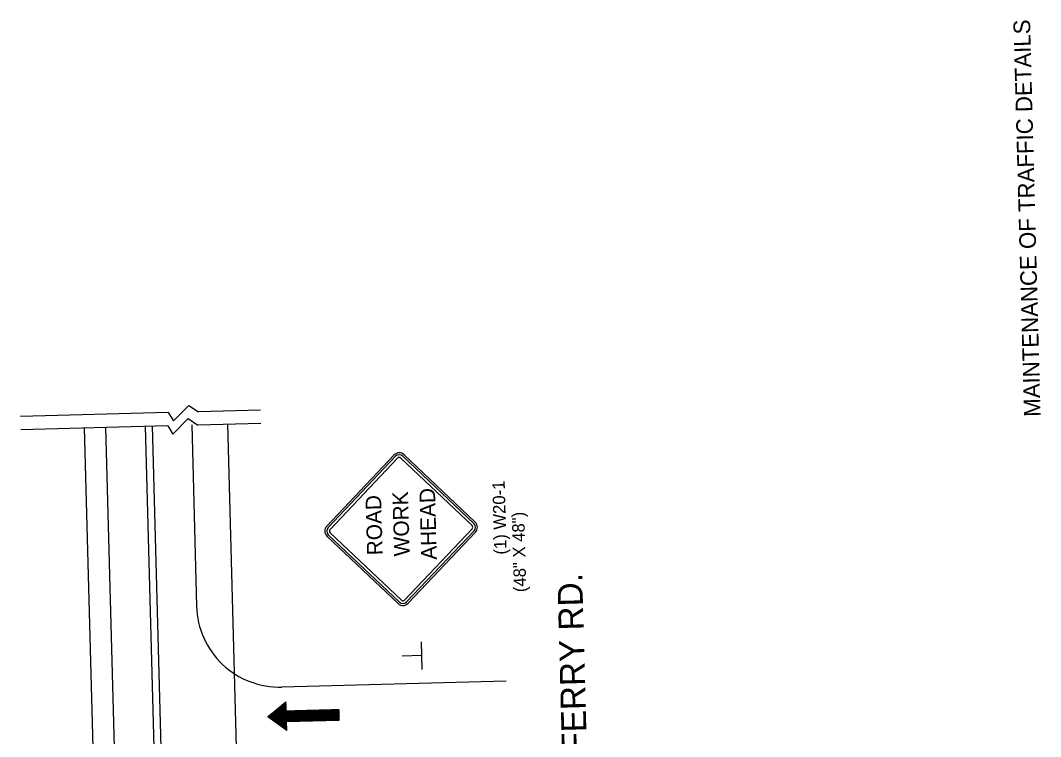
# Model space of a CAD drawing. Extents: x 1929653 to 1931621, y 596452 to 600944.
# Drawn here: x 1930855 to 1931592, y 598042 to 598560 of the extents above; entities that cross this region are included whole.
import ezdxf

# ---------------------------------------------------------------- set-up
doc = ezdxf.new("R2010")
doc.units = 0
for name, color, linetype in [('P_TC_Signs_Temporary', 7, 'Continuous'), ('R_Border', 7, 'Continuous'), ('R_Draft', 7, 'Continuous')]:
    doc.layers.add(name, color=color, linetype=linetype)

msp = doc.modelspace()

# ---------------------------------------------------------------- linework, layer by layer
at = {"layer": 'P_TC_Signs_Temporary'}
for p, q in [((1931124.99, 598245.86), (1931076.24, 598194.42)), ((1931126.01, 598244.9), (1931077.26, 598193.45)), ((1931182.62, 598196.28), (1931131.18, 598245.04)), ((1931183.59, 598197.3), (1931132.15, 598246.06)), ((1931127.44, 598243.54), (1931078.69, 598192.1)), ((1931181.27, 598194.85), (1931129.82, 598243.61)), ((1931076.43, 598187.26), (1931127.87, 598138.51)), ((1931077.4, 598188.28), (1931128.84, 598139.53)), ((1931078.75, 598189.71), (1931130.19, 598140.96)), ((1931132.58, 598141.02), (1931181.33, 598192.47)), ((1931134.01, 598139.67), (1931182.76, 598191.11)), ((1931135.03, 598138.7), (1931183.78, 598190.15))]:
    msp.add_line(p, q, dxfattribs=at)
for centre, radius, start, end in [((1931128.66, 598242.38), 5.06, 46.53769, 136.53769), ((1931128.66, 598242.38), 3.66, 46.53769, 136.53769), ((1931128.66, 598242.38), 1.69, 46.53769, 136.53769), ((1931079.91, 598190.94), 5.06, 136.53769, 226.53769), ((1931079.91, 598190.94), 3.66, 136.53769, 226.53769), ((1931180.11, 598193.63), 1.69, 316.53769, 46.53769), ((1931180.11, 598193.63), 3.66, 316.53769, 46.53769), ((1931180.11, 598193.63), 5.06, 316.53769, 46.53769), ((1931079.91, 598190.94), 1.69, 136.53769, 226.53769), ((1931131.35, 598142.18), 5.06, 226.53769, 316.53769), ((1931131.35, 598142.18), 3.66, 226.53769, 316.53769), ((1931131.35, 598142.18), 1.69, 226.53769, 316.53769)]:
    msp.add_arc(centre, radius, start, end, dxfattribs=at)
at = {"layer": 'R_Border'}
for p, q in [((1931038.76, 598060.91), (1931034.33, 598056.24)), ((1931039.54, 598061.55), (1931034.43, 598056.16)), ((1931040.32, 598062.19), (1931034.54, 598056.08)), ((1931041.11, 598062.83), (1931034.64, 598056)), ((1931041.89, 598063.46), (1931034.75, 598055.93)), ((1931042.68, 598064.1), (1931034.85, 598055.85)), ((1931043.46, 598064.74), (1931034.96, 598055.77)), ((1931044.24, 598065.38), (1931035.07, 598055.7)), ((1931045.03, 598066.01), (1931035.17, 598055.62)), ((1931045.81, 598066.65), (1931035.28, 598055.54)), ((1931046.59, 598067.29), (1931035.38, 598055.46)), ((1931046.82, 598067.34), (1931035.49, 598055.39)), ((1931046.82, 598067.16), (1931035.6, 598055.31)), ((1931046.83, 598066.97), (1931035.7, 598055.23)), ((1931046.83, 598066.79), (1931035.81, 598055.16)), ((1931046.84, 598066.61), (1931035.91, 598055.08)), ((1931046.84, 598066.42), (1931036.02, 598055)), ((1931046.85, 598066.24), (1931036.13, 598054.92)), ((1931046.85, 598066.05), (1931036.23, 598054.85)), ((1931046.86, 598065.87), (1931036.34, 598054.77)), ((1931046.86, 598065.69), (1931036.44, 598054.69)), ((1931046.87, 598065.5), (1931036.55, 598054.62)), ((1931046.87, 598065.32), (1931036.66, 598054.54)), ((1931046.88, 598065.14), (1931036.76, 598054.46)), ((1931046.88, 598064.95), (1931036.87, 598054.38)), ((1931046.89, 598064.77), (1931036.97, 598054.31)), ((1931046.89, 598064.58), (1931037.08, 598054.23)), ((1931046.9, 598064.4), (1931037.19, 598054.15)), ((1931046.9, 598064.22), (1931037.29, 598054.07)), ((1931046.91, 598064.03), (1931037.4, 598054)), ((1931046.91, 598063.85), (1931037.5, 598053.92)), ((1931046.92, 598063.67), (1931037.61, 598053.84)), ((1931046.92, 598063.48), (1931037.72, 598053.77)), ((1931046.93, 598063.3), (1931037.82, 598053.69)), ((1931046.93, 598063.11), (1931037.93, 598053.61)), ((1931046.94, 598062.93), (1931038.03, 598053.53)), ((1931046.94, 598062.75), (1931038.14, 598053.46)), ((1931046.95, 598062.56), (1931038.25, 598053.38)), ((1931046.95, 598062.38), (1931038.35, 598053.3)), ((1931046.96, 598062.19), (1931038.46, 598053.23)), ((1931046.96, 598062.01), (1931038.56, 598053.15)), ((1931046.97, 598061.83), (1931038.67, 598053.07)), ((1931046.97, 598061.64), (1931038.78, 598052.99)), ((1931046.98, 598061.46), (1931038.88, 598052.92)), ((1931046.98, 598061.28), (1931038.99, 598052.84)), ((1931046.99, 598061.09), (1931039.09, 598052.76)), ((1931047.07, 598060.99), (1931039.2, 598052.69)), ((1931047.26, 598061), (1931039.31, 598052.61)), ((1931047.44, 598061), (1931039.41, 598052.53)), ((1931047.62, 598061.01), (1931039.52, 598052.45)), ((1931047.81, 598061.01), (1931039.62, 598052.38)), ((1931047.99, 598061.02), (1931039.73, 598052.3)), ((1931048.18, 598061.02), (1931039.84, 598052.22)), ((1931048.36, 598061.03), (1931039.94, 598052.15)), ((1931048.54, 598061.03), (1931040.05, 598052.07)), ((1931048.73, 598061.04), (1931040.15, 598051.99)), ((1931048.91, 598061.04), (1931040.26, 598051.91)), ((1931049.09, 598061.05), (1931040.37, 598051.84)), ((1931049.28, 598061.05), (1931040.47, 598051.76)), ((1931049.46, 598061.06), (1931040.58, 598051.68)), ((1931049.65, 598061.06), (1931040.68, 598051.61)), ((1931049.83, 598061.07), (1931040.79, 598051.53)), ((1931050.01, 598061.07), (1931040.89, 598051.45)), ((1931050.2, 598061.08), (1931041, 598051.37)), ((1931050.38, 598061.08), (1931041.11, 598051.3)), ((1931050.56, 598061.09), (1931041.21, 598051.22)), ((1931050.75, 598061.09), (1931041.32, 598051.14)), ((1931050.93, 598061.1), (1931041.42, 598051.06)), ((1931051.12, 598061.1), (1931041.53, 598050.99)), ((1931051.3, 598061.11), (1931041.64, 598050.91)), ((1931051.48, 598061.11), (1931041.74, 598050.83)), ((1931051.67, 598061.12), (1931041.85, 598050.76)), ((1931051.85, 598061.12), (1931041.95, 598050.68)), ((1931052.03, 598061.13), (1931042.06, 598050.6)), ((1931052.22, 598061.13), (1931042.17, 598050.52)), ((1931052.4, 598061.14), (1931042.27, 598050.45)), ((1931052.59, 598061.14), (1931042.38, 598050.37)), ((1931052.77, 598061.15), (1931042.48, 598050.29)), ((1931052.95, 598061.15), (1931042.59, 598050.22)), ((1931053.14, 598061.16), (1931042.7, 598050.14)), ((1931053.32, 598061.16), (1931042.8, 598050.06)), ((1931053.5, 598061.17), (1931042.91, 598049.98)), ((1931053.69, 598061.17), (1931043.01, 598049.91)), ((1931053.87, 598061.18), (1931043.12, 598049.83)), ((1931054.06, 598061.18), (1931043.23, 598049.75)), ((1931054.24, 598061.19), (1931043.33, 598049.68)), ((1931054.42, 598061.19), (1931043.44, 598049.6)), ((1931054.61, 598061.2), (1931043.54, 598049.52)), ((1931054.79, 598061.2), (1931047.22, 598053.21)), ((1931054.98, 598061.21), (1931047.41, 598053.22)), ((1931055.16, 598061.21), (1931047.59, 598053.22)), ((1931055.34, 598061.22), (1931047.77, 598053.23)), ((1931055.53, 598061.22), (1931047.96, 598053.23)), ((1931055.71, 598061.23), (1931048.14, 598053.24)), ((1931055.89, 598061.23), (1931048.33, 598053.24)), ((1931056.08, 598061.23), (1931048.51, 598053.25)), ((1931056.26, 598061.24), (1931048.69, 598053.25)), ((1931056.45, 598061.24), (1931048.88, 598053.26)), ((1931056.63, 598061.25), (1931049.06, 598053.26)), ((1931056.81, 598061.25), (1931049.24, 598053.27)), ((1931057, 598061.26), (1931049.43, 598053.27)), ((1931057.18, 598061.26), (1931049.61, 598053.28)), ((1931057.36, 598061.27), (1931049.8, 598053.28)), ((1931057.55, 598061.27), (1931049.98, 598053.29)), ((1931057.73, 598061.28), (1931050.16, 598053.29)), ((1931057.92, 598061.28), (1931050.35, 598053.3)), ((1931058.1, 598061.29), (1931050.53, 598053.3)), ((1931058.28, 598061.29), (1931050.71, 598053.31)), ((1931058.47, 598061.3), (1931050.9, 598053.31)), ((1931058.65, 598061.3), (1931051.08, 598053.32)), ((1931058.83, 598061.31), (1931051.27, 598053.32)), ((1931059.02, 598061.31), (1931051.45, 598053.33)), ((1931059.2, 598061.32), (1931051.63, 598053.33)), ((1931059.39, 598061.32), (1931051.82, 598053.34)), ((1931059.57, 598061.33), (1931052, 598053.34)), ((1931059.75, 598061.33), (1931052.19, 598053.35)), ((1931059.94, 598061.34), (1931052.37, 598053.35)), ((1931060.12, 598061.34), (1931052.55, 598053.36)), ((1931060.3, 598061.35), (1931052.74, 598053.36)), ((1931060.49, 598061.35), (1931052.92, 598053.37)), ((1931060.67, 598061.36), (1931053.1, 598053.37)), ((1931060.86, 598061.36), (1931053.29, 598053.38)), ((1931061.04, 598061.37), (1931053.47, 598053.38)), ((1931061.22, 598061.37), (1931053.66, 598053.39)), ((1931061.41, 598061.38), (1931053.84, 598053.39)), ((1931061.59, 598061.38), (1931054.02, 598053.4)), ((1931061.78, 598061.39), (1931054.21, 598053.4)), ((1931061.96, 598061.39), (1931054.39, 598053.41)), ((1931062.14, 598061.4), (1931054.57, 598053.41)), ((1931062.33, 598061.4), (1931054.76, 598053.42)), ((1931062.51, 598061.41), (1931054.94, 598053.42)), ((1931062.69, 598061.41), (1931055.13, 598053.43)), ((1931062.88, 598061.42), (1931055.31, 598053.43)), ((1931063.06, 598061.42), (1931055.49, 598053.44)), ((1931063.25, 598061.43), (1931055.68, 598053.44)), ((1931063.43, 598061.43), (1931055.86, 598053.45)), ((1931063.61, 598061.44), (1931056.04, 598053.45)), ((1931063.8, 598061.44), (1931056.23, 598053.46)), ((1931063.98, 598061.45), (1931056.41, 598053.46)), ((1931064.16, 598061.45), (1931056.6, 598053.47)), ((1931064.35, 598061.46), (1931056.78, 598053.47)), ((1931064.53, 598061.46), (1931056.96, 598053.48)), ((1931064.72, 598061.47), (1931057.15, 598053.48)), ((1931064.9, 598061.47), (1931057.33, 598053.49)), ((1931065.08, 598061.48), (1931057.51, 598053.49)), ((1931065.27, 598061.48), (1931057.7, 598053.5)), ((1931065.45, 598061.49), (1931057.88, 598053.5)), ((1931065.63, 598061.49), (1931058.07, 598053.51)), ((1931065.82, 598061.5), (1931058.25, 598053.51)), ((1931066, 598061.5), (1931058.43, 598053.52)), ((1931066.19, 598061.51), (1931058.62, 598053.52)), ((1931066.37, 598061.51), (1931058.8, 598053.53)), ((1931066.55, 598061.52), (1931058.99, 598053.53)), ((1931066.74, 598061.52), (1931059.17, 598053.54)), ((1931066.92, 598061.53), (1931059.35, 598053.54)), ((1931067.1, 598061.53), (1931059.54, 598053.54)), ((1931067.29, 598061.54), (1931059.72, 598053.55)), ((1931067.47, 598061.54), (1931059.9, 598053.55)), ((1931067.66, 598061.55), (1931060.09, 598053.56)), ((1931067.84, 598061.55), (1931060.27, 598053.56)), ((1931068.02, 598061.56), (1931060.46, 598053.57)), ((1931068.21, 598061.56), (1931060.64, 598053.57)), ((1931068.39, 598061.57), (1931060.82, 598053.58)), ((1931068.58, 598061.57), (1931061.01, 598053.58)), ((1931068.76, 598061.58), (1931061.19, 598053.59)), ((1931068.94, 598061.58), (1931061.37, 598053.59)), ((1931069.13, 598061.59), (1931061.56, 598053.6)), ((1931069.31, 598061.59), (1931061.74, 598053.6)), ((1931069.49, 598061.6), (1931061.93, 598053.61)), ((1931069.68, 598061.6), (1931062.11, 598053.61)), ((1931069.86, 598061.6), (1931062.29, 598053.62)), ((1931070.05, 598061.61), (1931062.48, 598053.62)), ((1931070.23, 598061.61), (1931062.66, 598053.63)), ((1931070.41, 598061.62), (1931062.84, 598053.63)), ((1931070.6, 598061.62), (1931063.03, 598053.64)), ((1931070.78, 598061.63), (1931063.21, 598053.64)), ((1931070.96, 598061.63), (1931063.4, 598053.65)), ((1931071.15, 598061.64), (1931063.58, 598053.65)), ((1931071.33, 598061.64), (1931063.76, 598053.66)), ((1931071.52, 598061.65), (1931063.95, 598053.66)), ((1931071.7, 598061.65), (1931064.13, 598053.67)), ((1931071.88, 598061.66), (1931064.31, 598053.67)), ((1931072.07, 598061.66), (1931064.5, 598053.68)), ((1931072.25, 598061.67), (1931064.68, 598053.68)), ((1931072.43, 598061.67), (1931064.87, 598053.69)), ((1931072.62, 598061.68), (1931065.05, 598053.69)), ((1931072.8, 598061.68), (1931065.23, 598053.7)), ((1931072.99, 598061.69), (1931065.42, 598053.7)), ((1931073.17, 598061.69), (1931065.6, 598053.71)), ((1931073.35, 598061.7), (1931065.78, 598053.71)), ((1931073.54, 598061.7), (1931065.97, 598053.72)), ((1931073.72, 598061.71), (1931066.15, 598053.72)), ((1931073.9, 598061.71), (1931066.34, 598053.73)), ((1931074.09, 598061.72), (1931066.52, 598053.73)), ((1931074.27, 598061.72), (1931066.7, 598053.74)), ((1931074.46, 598061.73), (1931066.89, 598053.74)), ((1931074.64, 598061.73), (1931067.07, 598053.75)), ((1931074.82, 598061.74), (1931067.26, 598053.75)), ((1931075.01, 598061.74), (1931067.44, 598053.76)), ((1931075.19, 598061.75), (1931067.62, 598053.76)), ((1931075.37, 598061.75), (1931067.81, 598053.77)), ((1931075.56, 598061.76), (1931067.99, 598053.77)), ((1931075.74, 598061.76), (1931068.17, 598053.78)), ((1931075.93, 598061.77), (1931068.36, 598053.78)), ((1931076.11, 598061.77), (1931068.54, 598053.79)), ((1931076.29, 598061.78), (1931068.73, 598053.79)), ((1931076.48, 598061.78), (1931068.91, 598053.8)), ((1931076.66, 598061.79), (1931069.09, 598053.8)), ((1931076.85, 598061.79), (1931069.28, 598053.81)), ((1931077.03, 598061.8), (1931069.46, 598053.81)), ((1931077.21, 598061.8), (1931069.64, 598053.82)), ((1931077.4, 598061.81), (1931069.83, 598053.82)), ((1931077.58, 598061.81), (1931070.01, 598053.83)), ((1931077.76, 598061.82), (1931070.2, 598053.83)), ((1931077.95, 598061.82), (1931070.38, 598053.84)), ((1931078.13, 598061.83), (1931070.56, 598053.84)), ((1931078.32, 598061.83), (1931070.75, 598053.85)), ((1931078.5, 598061.84), (1931070.93, 598053.85)), ((1931078.68, 598061.84), (1931071.11, 598053.86)), ((1931078.87, 598061.85), (1931071.3, 598053.86)), ((1931079.05, 598061.85), (1931071.48, 598053.87)), ((1931079.23, 598061.86), (1931071.67, 598053.87)), ((1931079.42, 598061.86), (1931071.85, 598053.88)), ((1931079.6, 598061.87), (1931072.03, 598053.88)), ((1931079.79, 598061.87), (1931072.22, 598053.89)), ((1931079.97, 598061.88), (1931072.4, 598053.89)), ((1931080.15, 598061.88), (1931072.58, 598053.9)), ((1931080.34, 598061.89), (1931072.77, 598053.9)), ((1931080.52, 598061.89), (1931072.95, 598053.91)), ((1931080.7, 598061.9), (1931073.14, 598053.91)), ((1931080.89, 598061.9), (1931073.32, 598053.91)), ((1931081.07, 598061.91), (1931073.5, 598053.92)), ((1931081.26, 598061.91), (1931073.69, 598053.92)), ((1931081.44, 598061.92), (1931073.87, 598053.93)), ((1931081.62, 598061.92), (1931074.06, 598053.93)), ((1931081.81, 598061.93), (1931074.24, 598053.94)), ((1931081.99, 598061.93), (1931074.42, 598053.94)), ((1931082.17, 598061.94), (1931074.61, 598053.95)), ((1931082.36, 598061.94), (1931074.79, 598053.95)), ((1931082.54, 598061.95), (1931074.97, 598053.96)), ((1931082.73, 598061.95), (1931075.16, 598053.96)), ((1931082.91, 598061.96), (1931075.34, 598053.97)), ((1931083.09, 598061.96), (1931075.53, 598053.97)), ((1931083.28, 598061.97), (1931075.71, 598053.98)), ((1931083.46, 598061.97), (1931075.89, 598053.98)), ((1931083.65, 598061.97), (1931076.08, 598053.99)), ((1931083.83, 598061.98), (1931076.26, 598053.99)), ((1931084.01, 598061.98), (1931076.44, 598054)), ((1931084.2, 598061.99), (1931076.63, 598054)), ((1931084.38, 598061.99), (1931076.81, 598054.01)), ((1931084.56, 598062), (1931077, 598054.01)), ((1931084.75, 598062), (1931077.18, 598054.02)), ((1931084.93, 598062.01), (1931077.36, 598054.02)), ((1931085.12, 598062.01), (1931077.55, 598054.03)), ((1931085.13, 598061.84), (1931077.73, 598054.03)), ((1931085.14, 598061.66), (1931077.91, 598054.04)), ((1931085.14, 598061.48), (1931078.1, 598054.04)), ((1931085.15, 598061.29), (1931078.28, 598054.05)), ((1931085.15, 598061.11), (1931078.47, 598054.05)), ((1931085.16, 598060.92), (1931078.65, 598054.06)), ((1931085.16, 598060.74), (1931078.83, 598054.06)), ((1931085.17, 598060.56), (1931079.02, 598054.07)), ((1931085.17, 598060.37), (1931079.2, 598054.07)), ((1931034.06, 598057.09), (1931033.69, 598056.7)), ((1931034.84, 598057.73), (1931033.8, 598056.62)), ((1931035.62, 598058.36), (1931033.9, 598056.54)), ((1931036.41, 598059), (1931034.01, 598056.47)), ((1931037.19, 598059.64), (1931034.11, 598056.39)), ((1931037.97, 598060.28), (1931034.22, 598056.31)), ((1931047.2, 598053.19), (1931043.65, 598049.44)), ((1931047.2, 598053.01), (1931043.76, 598049.37)), ((1931085.18, 598060.19), (1931079.38, 598054.08)), ((1931085.18, 598060.01), (1931079.57, 598054.08)), ((1931085.19, 598059.82), (1931079.75, 598054.09)), ((1931085.19, 598059.64), (1931079.94, 598054.09)), ((1931085.2, 598059.45), (1931080.12, 598054.1)), ((1931085.2, 598059.27), (1931080.3, 598054.1)), ((1931085.21, 598059.09), (1931080.49, 598054.11)), ((1931085.21, 598058.9), (1931080.67, 598054.11)), ((1931085.22, 598058.72), (1931080.86, 598054.12)), ((1931085.22, 598058.54), (1931081.04, 598054.12)), ((1931085.23, 598058.35), (1931081.22, 598054.13)), ((1931085.23, 598058.17), (1931081.41, 598054.13)), ((1931085.24, 598057.98), (1931081.59, 598054.14)), ((1931085.24, 598057.8), (1931081.77, 598054.14)), ((1931085.25, 598057.62), (1931081.96, 598054.15)), ((1931085.25, 598057.43), (1931082.14, 598054.15)), ((1931085.26, 598057.25), (1931082.33, 598054.16)), ((1931085.26, 598057.07), (1931082.51, 598054.16)), ((1931085.27, 598056.88), (1931082.69, 598054.17)), ((1931085.27, 598056.7), (1931082.88, 598054.17)), ((1931085.28, 598056.51), (1931083.06, 598054.18)), ((1931085.28, 598056.33), (1931083.24, 598054.18)), ((1931085.29, 598056.15), (1931083.43, 598054.19)), ((1931085.29, 598055.96), (1931083.61, 598054.19)), ((1931085.3, 598055.78), (1931083.8, 598054.2)), ((1931085.3, 598055.59), (1931083.98, 598054.2)), ((1931085.31, 598055.41), (1931084.16, 598054.21)), ((1931085.31, 598055.23), (1931084.35, 598054.21)), ((1931085.32, 598055.04), (1931084.53, 598054.22)), ((1931085.32, 598054.86), (1931084.71, 598054.22)), ((1931085.32, 598054.68), (1931084.9, 598054.23)), ((1931085.33, 598054.49), (1931085.08, 598054.23)), ((1931085.33, 598054.31), (1931085.27, 598054.24)), ((1931047.21, 598052.82), (1931043.86, 598049.29)), ((1931047.21, 598052.64), (1931043.97, 598049.21)), ((1931047.22, 598052.45), (1931044.07, 598049.14)), ((1931047.22, 598052.27), (1931044.18, 598049.06)), ((1931047.23, 598052.09), (1931044.29, 598048.98)), ((1931047.23, 598051.9), (1931044.39, 598048.9)), ((1931047.24, 598051.72), (1931044.5, 598048.83)), ((1931047.24, 598051.54), (1931044.6, 598048.75)), ((1931047.25, 598051.35), (1931044.71, 598048.67)), ((1931047.25, 598051.17), (1931044.82, 598048.6)), ((1931047.26, 598050.98), (1931044.92, 598048.52)), ((1931047.26, 598050.8), (1931045.03, 598048.44)), ((1931047.27, 598050.62), (1931045.13, 598048.36)), ((1931047.27, 598050.43), (1931045.24, 598048.29)), ((1931047.28, 598050.25), (1931045.35, 598048.21)), ((1931047.28, 598050.07), (1931045.45, 598048.13)), ((1931047.29, 598049.88), (1931045.56, 598048.06)), ((1931047.29, 598049.7), (1931045.66, 598047.98)), ((1931047.3, 598049.51), (1931045.77, 598047.9)), ((1931047.3, 598049.33), (1931045.88, 598047.82)), ((1931047.31, 598049.15), (1931045.98, 598047.75)), ((1931047.31, 598048.96), (1931046.09, 598047.67)), ((1931047.32, 598048.78), (1931046.19, 598047.59)), ((1931047.32, 598048.6), (1931046.3, 598047.51)), ((1931047.33, 598048.41), (1931046.41, 598047.44)), ((1931047.33, 598048.23), (1931046.51, 598047.36)), ((1931047.34, 598048.04), (1931046.62, 598047.28)), ((1931047.34, 598047.86), (1931046.72, 598047.21)), ((1931047.35, 598047.68), (1931046.83, 598047.13)), ((1931047.35, 598047.49), (1931046.93, 598047.05)), ((1931047.36, 598047.31), (1931047.04, 598046.97)), ((1931047.36, 598047.12), (1931047.15, 598046.9)), ((1931047.37, 598046.94), (1931047.25, 598046.82)), ((1931047.37, 598046.76), (1931047.36, 598046.74))]:
    msp.add_line(p, q, dxfattribs=at)
at = {"layer": 'R_Draft'}
for p, q in [((1930961.75, 598276.49), (1930854.89, 598273.62)), ((1931028.33, 598278.27), (1930983.56, 598277.07)), ((1930961.32, 598266.89), (1930855.15, 598264.04)), ((1930950.2, 598266.8), (1930974.7, 597354.16)), ((1930978.71, 598267.57), (1930982.23, 598136.56)), ((1931028.59, 598268.7), (1930983.14, 598267.48)), ((1931004.63, 598268.26), (1931029.13, 597355.62)), ((1930900.94, 598265.48), (1930925.44, 597352.83)), ((1930916.49, 598265.9), (1930935.8, 597546.71)), ((1930945, 598266.66), (1930969.5, 597354.02)), ((1931144.57, 598110.99), (1931145.11, 598090.8)), ((1931144.55, 598100.94), (1931130.77, 598100.57)), ((1931205.9, 598082.55), (1931043.81, 598078.2)), ((1931033.63, 598056.74), (1931046.82, 598067.47)), ((1931046.99, 598060.99), (1931046.82, 598067.47)), ((1931046.99, 598060.99), (1931085.13, 598062.01)), ((1931085.34, 598054.24), (1931085.13, 598062.01)), ((1931047.37, 598046.73), (1931033.63, 598056.74)), ((1931047.2, 598053.21), (1931085.34, 598054.24)), ((1931047.37, 598046.73), (1931047.2, 598053.21))]:
    msp.add_line(p, q, dxfattribs=at)
for points in [[(1930961.75, 598276.49), (1930965.57, 598270.46), (1930976.58, 598281.7), (1930983.56, 598277.07)], [(1930961.32, 598266.89), (1930965.14, 598260.86), (1930976.14, 598272.11), (1930983.14, 598267.48)]]:
    msp.add_lwpolyline(points, dxfattribs=at)
msp.add_arc((1931042.2, 598138.17), 60, 181.53768, 271.53769, dxfattribs=at)

# ---------------------------------------------------------------- texts
at = {"layer": 'P_TC_Signs_Temporary'}
for s, p in [(' ROAD ', (1931116.8, 598169.39)), ('WORK', (1931136.25, 598172.84)), (' AHEAD ', (1931155.97, 598166.1))]:
    msp.add_text(s, height=11.25, rotation=91.53769, dxfattribs=at).set_placement(p)
at = {"layer": 'R_Border'}
for s, height, p in [('MAINTENANCE OF TRAFFIC DETAILS', 12, (1931592.22, 598273.58)), ('(1) W20-1', 9, (1931206.31, 598174)), ('(48" X 48")', 9, (1931220.54, 598146.87)), ('BLACKS FERRY RD.', 18, (1931267.06, 597929.44))]:
    msp.add_text(s, height=height, rotation=91.53769, dxfattribs=at).set_placement(p)

doc.saveas('drawing.dxf')
